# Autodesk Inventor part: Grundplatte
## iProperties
Company: HERDT-Verlag
Created: 2006-01
Part Number: Grundplatte
Material: 1.0037 St 37-2
Document SubType Name: Modeling
Designer: Eichenseer
Project: Inventor 11 - Grundkurs
Checked By: G. Lehmann
Engr Approved By: M. Grouls
Description: DIN 1013 Ø190x30
Engineer: Käs
Author: P. Tropf
Subject: Inventor 10 - Grundkurs
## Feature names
1. Grundkörper [Extrusion]
2. Feder [Extrusion]
3. Langlöcher [Extrusion]
4. Bohrung1 [Hole]
5. Bohrung2 [Hole]
6. Bohrung3 [Hole]
7. Bohrung4 [Hole]
